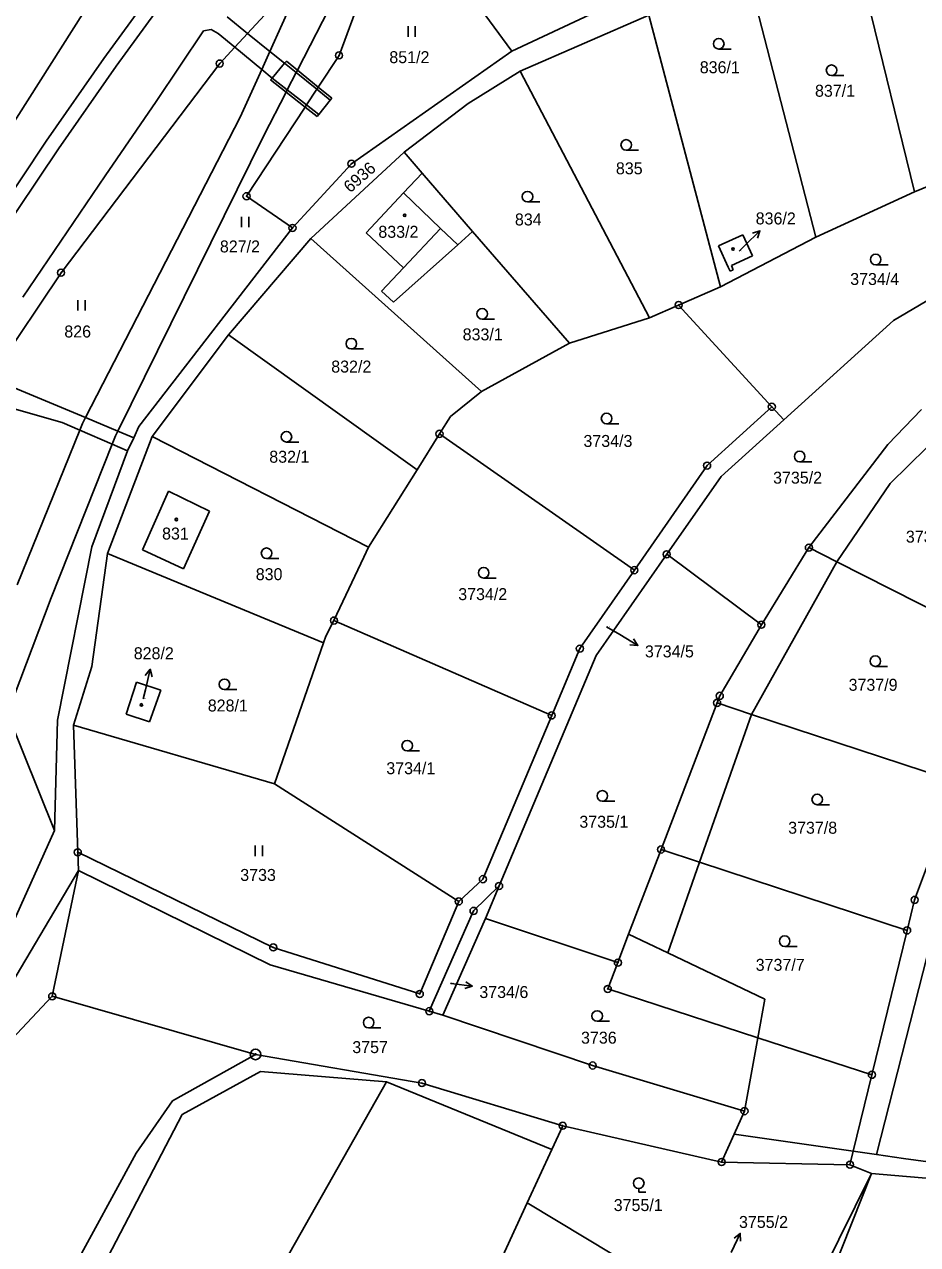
# Model space of a CAD drawing. Extents: x -593183 to -588034, y -1130415 to -1124994.
# Drawn here: x -592113.3 to -591986.4, y -1129180.7 to -1129007.5 of the extents above; entities that cross this region are included whole.
import ezdxf

# ---------------------------------------------------------------- set-up
doc = ezdxf.new("R2010")
doc.units = 0
for name, color, linetype in [('Vrstva 1', 7, 'Continuous'), ('Vrstva 16', 7, 'Continuous'), ('Vrstva 18', 7, 'Continuous'), ('Vrstva 19', 7, 'Continuous'), ('Vrstva 24', 7, 'Continuous'), ('Vrstva 25', 7, 'Continuous'), ('Vrstva 4', 7, 'Continuous')]:
    doc.layers.add(name, color=color, linetype=linetype)

msp = doc.modelspace()

# ---------------------------------------------------------------- linework, layer by layer
at = {"layer": 'Vrstva 1'}
for p, q in [((-592095.63, -1128991.25), (-592122.16, -1129033.04)), ((-592061.52, -1128993), (-592068.58, -1129011.91)), ((-592044.03, -1129011.3), (-592058.1, -1128992.14)), ((-592101.98, -1129012.35), (-592089.15, -1128994.78)), ((-592100.25, -1129013.46), (-592087.6, -1128996.06)), ((-591994.88, -1128998.43), (-591986.87, -1129031.29)), ((-592081.56, -1129008.78), (-592075.31, -1129002.03)), ((-592067.64, -1129000.62), (-592074.5, -1129014.01)), ((-592010.12, -1129001.94), (-592000.9, -1129037.72)), ((-592074.55, -1129002.77), (-592078.41, -1129011.34)), ((-592044.03, -1129011.3), (-592027.75, -1129003.63)), ((-592042.85, -1129014.16), (-592024.59, -1129006.21)), ((-592024.59, -1129006.21), (-592014.41, -1129044.75)), ((-592083.38, -1129010.75), (-592081.56, -1129008.78)), ((-592110.17, -1129024.09), (-592101.98, -1129012.35)), ((-592085.53, -1129013.07), (-592083.38, -1129010.75)), ((-592079.56, -1129013.91), (-592078.41, -1129011.34)), ((-592071.53, -1129016.4), (-592068.58, -1129011.91)), ((-592066.82, -1129027.29), (-592044.03, -1129011.3)), ((-592108.41, -1129025.19), (-592100.25, -1129013.46)), ((-592108.06, -1129042.75), (-592085.53, -1129013.07)), ((-592082.6, -1129020.67), (-592079.56, -1129013.91)), ((-592074.68, -1129014.35), (-592074.5, -1129014.01)), ((-592050.23, -1129018.75), (-592042.85, -1129014.16)), ((-592024.5, -1129049.14), (-592042.85, -1129014.16)), ((-592075.94, -1129016.81), (-592074.68, -1129014.35)), ((-592079.25, -1129023.26), (-592076.11, -1129017.13)), ((-592076.11, -1129017.13), (-592075.94, -1129016.81)), ((-592073.2, -1129018.94), (-592071.74, -1129016.71)), ((-592071.74, -1129016.71), (-592071.53, -1129016.4)), ((-592081.72, -1129031.9), (-592073.4, -1129019.25)), ((-592073.4, -1129019.25), (-592073.2, -1129018.94)), ((-592059.35, -1129025.66), (-592050.23, -1129018.75)), ((-592104.56, -1129063.33), (-592082.6, -1129020.67)), ((-591986.87, -1129031.29), (-591962.16, -1129021)), ((-592124.08, -1129044.93), (-592110.17, -1129024.09)), ((-592079.25, -1129023.26), (-592100, -1129065.24)), ((-592122.38, -1129045.9), (-592108.41, -1129025.19)), ((-592072.61, -1129037.9), (-592059.35, -1129025.66)), ((-592059.35, -1129025.66), (-592056.8, -1129028.61)), ((-592075.19, -1129036.4), (-592066.82, -1129027.29)), ((-592059.44, -1129031.43), (-592056.8, -1129028.61)), ((-592056.8, -1129028.61), (-592049.61, -1129036.91)), ((-592059.44, -1129031.43), (-592064.74, -1129037.09)), ((-592000.9, -1129037.72), (-591986.87, -1129031.29)), ((-592081.72, -1129031.9), (-592075.19, -1129036.4)), ((-591989.84, -1129049.54), (-591964.03, -1129034.3)), ((-592097.02, -1129064.6), (-592075.19, -1129036.4)), ((-592072.61, -1129037.9), (-592084.28, -1129051.58)), ((-592072.61, -1129037.9), (-592048.35, -1129059.62)), ((-592059.43, -1129042.06), (-592064.74, -1129037.09)), ((-592049.61, -1129036.91), (-592051.71, -1129038.78)), ((-592049.61, -1129036.91), (-592035.87, -1129052.78)), ((-592014.7, -1129038.95), (-592011.24, -1129037.37)), ((-592014.41, -1129044.75), (-592000.9, -1129037.72)), ((-592011.24, -1129037.37), (-592009.87, -1129040.37)), ((-592051.71, -1129038.78), (-592060.86, -1129046.95)), ((-592013.33, -1129041.95), (-592014.7, -1129038.95)), ((-592009.87, -1129040.37), (-592012.87, -1129041.75)), ((-592012.87, -1129041.75), (-592012.6, -1129042.34)), ((-592117.62, -1129057.03), (-592108.06, -1129042.75)), ((-592062.54, -1129045.38), (-592059.43, -1129042.06)), ((-592013.06, -1129042.55), (-592013.33, -1129041.95)), ((-592012.6, -1129042.34), (-592013.06, -1129042.55)), ((-592060.86, -1129046.95), (-592062.54, -1129045.38)), ((-592020.36, -1129047.34), (-592014.41, -1129044.75)), ((-592024.5, -1129049.14), (-592020.36, -1129047.34)), ((-592020.36, -1129047.34), (-592007.13, -1129061.79)), ((-592035.87, -1129052.78), (-592024.5, -1129049.14)), ((-592005.44, -1129063.63), (-591989.84, -1129049.54)), ((-592095.12, -1129066), (-592084.28, -1129051.58)), ((-592084.28, -1129051.58), (-592057.5, -1129070.72)), ((-592048.35, -1129059.62), (-592035.87, -1129052.78)), ((-592052.77, -1129063.17), (-592048.35, -1129059.62)), ((-592016.32, -1129070.14), (-592007.13, -1129061.79)), ((-592007.13, -1129061.79), (-592005.44, -1129063.63)), ((-591990.67, -1129067.13), (-591985.87, -1129062.19)), ((-592105.38, -1129065.12), (-592104.99, -1129064.16)), ((-592104.99, -1129064.16), (-592104.56, -1129063.33)), ((-592054.32, -1129065.63), (-592052.77, -1129063.17)), ((-592014.33, -1129071.66), (-592005.44, -1129063.63)), ((-592114.3, -1129087.06), (-592105.38, -1129065.12)), ((-592101.46, -1129082.61), (-592095.12, -1129066)), ((-592100.81, -1129067.11), (-592100.34, -1129065.92)), ((-592100, -1129065.24), (-592100.34, -1129065.92)), ((-592097.74, -1129066.19), (-592097.02, -1129064.6)), ((-592095.12, -1129066), (-592064.41, -1129081.73)), ((-592057.5, -1129070.72), (-592054.32, -1129065.63)), ((-592054.32, -1129065.63), (-592026.65, -1129084.98)), ((-592109.48, -1129088.92), (-592100.81, -1129067.11)), ((-592098.63, -1129068.06), (-592097.74, -1129066.19)), ((-592001.87, -1129081.78), (-591990.67, -1129067.13)), ((-592103.67, -1129081.65), (-592098.63, -1129068.06)), ((-592057.5, -1129070.72), (-592064.41, -1129081.73)), ((-592026.65, -1129084.98), (-592016.32, -1129070.14)), ((-592022.06, -1129082.73), (-592014.33, -1129071.66)), ((-592096.5, -1129082.09), (-592092.79, -1129073.78)), ((-592092.79, -1129073.78), (-592086.98, -1129076.61)), ((-592086.98, -1129076.61), (-592090.69, -1129084.78)), ((-592108.57, -1129106.26), (-592103.67, -1129081.65)), ((-592064.41, -1129081.73), (-592065.07, -1129083.14)), ((-592103.67, -1129098.65), (-592101.46, -1129082.61)), ((-592101.46, -1129082.61), (-592070.79, -1129095.3)), ((-592090.69, -1129084.78), (-592096.5, -1129082.09)), ((-592069.3, -1129092.13), (-592065.07, -1129083.14)), ((-592032.09, -1129097.08), (-592022.06, -1129082.73)), ((-592022.06, -1129082.73), (-592008.61, -1129092.72)), ((-592008.61, -1129092.72), (-592001.87, -1129081.78)), ((-592001.87, -1129081.78), (-591997.89, -1129083.8)), ((-592034.39, -1129096.11), (-592026.65, -1129084.98)), ((-591997.89, -1129083.8), (-591972.34, -1129096.74)), ((-592115.66, -1129105.33), (-592109.48, -1129088.92)), ((-592070.46, -1129094.36), (-592069.3, -1129092.13)), ((-592069.3, -1129092.13), (-592038.38, -1129105.6)), ((-592014.52, -1129102.82), (-592008.61, -1129092.72)), ((-592070.79, -1129095.3), (-592077.75, -1129115.29)), ((-592070.46, -1129094.36), (-592070.79, -1129095.3)), ((-592045.85, -1129129.81), (-592032.09, -1129097.08)), ((-592038.38, -1129105.6), (-592034.39, -1129096.11)), ((-592105.35, -1129103.97), (-592103.67, -1129098.65)), ((-592098.81, -1129105.4), (-592097.34, -1129100.88)), ((-592097.34, -1129100.88), (-592093.91, -1129101.99)), ((-592093.91, -1129101.99), (-592095.48, -1129106.49)), ((-592105.35, -1129103.97), (-592106.27, -1129106.98)), ((-592014.9, -1129103.82), (-592022.86, -1129124.63)), ((-592014.52, -1129102.82), (-592014.9, -1129103.82)), ((-592014.9, -1129103.82), (-592010.03, -1129105.49)), ((-592115.66, -1129105.33), (-592108.98, -1129121.92)), ((-592095.48, -1129106.49), (-592098.81, -1129105.4)), ((-592038.38, -1129105.6), (-592048.16, -1129128.84)), ((-592010.03, -1129105.49), (-591980.64, -1129115.09)), ((-592108.98, -1129121.92), (-592108.57, -1129106.26)), ((-592106.27, -1129106.98), (-592105.68, -1129125.02)), ((-592106.27, -1129106.98), (-592077.75, -1129115.29)), ((-592077.75, -1129115.29), (-592051.58, -1129132)), ((-591980.64, -1129115.09), (-591986.86, -1129131.78)), ((-592108.98, -1129121.92), (-592117.72, -1129141.31)), ((-592105.6, -1129127.62), (-592105.68, -1129125.02)), ((-592105.68, -1129125.02), (-592077.93, -1129138.52)), ((-592027.46, -1129136.67), (-592022.86, -1129124.63)), ((-592022.86, -1129124.63), (-592017.38, -1129126.43)), ((-592017.38, -1129126.43), (-591987.92, -1129136.12)), ((-592109.31, -1129145.46), (-592105.6, -1129127.62)), ((-592105.6, -1129127.62), (-592078.34, -1129140.99)), ((-592051.58, -1129132), (-592048.16, -1129128.84)), ((-592049.48, -1129133.34), (-592045.85, -1129129.81)), ((-592045.85, -1129129.81), (-592047.79, -1129134.42)), ((-591986.86, -1129131.78), (-591987.92, -1129136.12)), ((-592051.58, -1129132), (-592057.12, -1129145.14)), ((-592049.48, -1129133.34), (-592055.77, -1129147.58)), ((-592053.85, -1129148.14), (-592047.79, -1129134.42)), ((-592047.79, -1129134.42), (-592028.99, -1129140.69)), ((-592028.99, -1129140.69), (-592027.46, -1129136.67)), ((-591987.92, -1129136.12), (-591992.92, -1129156.61)), ((-592057.12, -1129145.14), (-592077.93, -1129138.52)), ((-592078.34, -1129140.99), (-592055.77, -1129147.58)), ((-592028.99, -1129140.69), (-592030.42, -1129144.42)), ((-592117.22, -1129153.83), (-592109.31, -1129145.46)), ((-592109.31, -1129145.46), (-592080.44, -1129153.72)), ((-592009.12, -1129151.34), (-592030.42, -1129144.42)), ((-592055.77, -1129147.58), (-592053.85, -1129148.14)), ((-592053.85, -1129148.14), (-592032.57, -1129155.29)), ((-591992.92, -1129156.61), (-592009.12, -1129151.34)), ((-592080.44, -1129153.72), (-592092.21, -1129160.3)), ((-592080.44, -1129153.72), (-592056.81, -1129157.78)), ((-592090.87, -1129162.25), (-592079.74, -1129156.12)), ((-592079.74, -1129156.12), (-592061.84, -1129157.63)), ((-592032.57, -1129155.29), (-592011.01, -1129161.77)), ((-592061.84, -1129157.63), (-592104.33, -1129232.5)), ((-592061.84, -1129157.63), (-592038.38, -1129167.21)), ((-592056.81, -1129157.78), (-592036.82, -1129163.84)), ((-591992.92, -1129156.61), (-591995.57, -1129167.46)), ((-592092.21, -1129160.3), (-592097.37, -1129167.74)), ((-592109.38, -1129197.76), (-592090.87, -1129162.25)), ((-592011.01, -1129161.77), (-592012.48, -1129165.04)), ((-592038.38, -1129167.21), (-592036.82, -1129163.84)), ((-592036.82, -1129163.84), (-592014.26, -1129168.99)), ((-592012.48, -1129165.04), (-592014.26, -1129168.99)), ((-592097.37, -1129167.74), (-592113.04, -1129196.42)), ((-592038.38, -1129167.21), (-592041.87, -1129174.78)), ((-591995.57, -1129167.46), (-591996.03, -1129169.37)), ((-592014.26, -1129168.99), (-591996.03, -1129169.37)), ((-591996.03, -1129169.37), (-591992.96, -1129170.62)), ((-592002.9, -1129190.64), (-591992.96, -1129170.62)), ((-591992.96, -1129170.62), (-592001.29, -1129191.44)), ((-591992.96, -1129170.62), (-591976.63, -1129172.04)), ((-592046.75, -1129185.36), (-592041.87, -1129174.78)), ((-592041.87, -1129174.78), (-592008.37, -1129194.92))]:
    msp.add_line(p, q, dxfattribs=at)
at = {"layer": 'Vrstva 16'}
for p, q in [((-592011.79, -1129039.7), (-592010.96, -1129038.89)), ((-592030.59, -1129093.02), (-592028.73, -1129094.13)), ((-592096.39, -1129103.25), (-592096.08, -1129101.97)), ((-592052.77, -1129143.61), (-592052.64, -1129143.63))]:
    msp.add_line(p, q, dxfattribs=at)
at = {"layer": 'Vrstva 24'}
for centre, radius in [((-592068.58, -1129011.91), 0.5), ((-592068.58, -1129011.91), 0.0327), ((-592085.53, -1129013.07), 0.5), ((-592085.53, -1129013.07), 0.0327), ((-592066.82, -1129027.29), 0.5), ((-592066.82, -1129027.29), 0.0327), ((-592081.72, -1129031.9), 0.5), ((-592081.72, -1129031.9), 0.0327), ((-592075.19, -1129036.4), 0.5), ((-592075.19, -1129036.4), 0.0327), ((-592108.06, -1129042.75), 0.5), ((-592108.06, -1129042.75), 0.0327), ((-592020.36, -1129047.34), 0.5), ((-592020.36, -1129047.34), 0.0327), ((-592007.13, -1129061.79), 0.5), ((-592007.13, -1129061.79), 0.0327), ((-592054.32, -1129065.63), 0.5), ((-592054.32, -1129065.63), 0.0327), ((-592016.32, -1129070.14), 0.5), ((-592016.32, -1129070.14), 0.0327), ((-592001.87, -1129081.78), 0.5), ((-592001.87, -1129081.78), 0.0327), ((-592022.06, -1129082.73), 0.5), ((-592022.06, -1129082.73), 0.0327), ((-592026.65, -1129084.98), 0.5), ((-592026.65, -1129084.98), 0.0327), ((-592069.3, -1129092.13), 0.5), ((-592069.3, -1129092.13), 0.0327), ((-592008.61, -1129092.72), 0.5), ((-592008.61, -1129092.72), 0.0327), ((-592034.39, -1129096.11), 0.5), ((-592034.39, -1129096.11), 0.0327), ((-592014.52, -1129102.82), 0.5), ((-592014.9, -1129103.82), 0.5), ((-592014.9, -1129103.82), 0.0327), ((-592014.52, -1129102.82), 0.0327), ((-592038.38, -1129105.6), 0.5), ((-592038.38, -1129105.6), 0.0327), ((-592105.68, -1129125.02), 0.5), ((-592105.68, -1129125.02), 0.0327), ((-592022.86, -1129124.63), 0.5), ((-592022.86, -1129124.63), 0.0327), ((-592048.16, -1129128.84), 0.5), ((-592048.16, -1129128.84), 0.0327), ((-592045.85, -1129129.81), 0.5), ((-592045.85, -1129129.81), 0.0327), ((-592051.58, -1129132), 0.5), ((-592051.58, -1129132), 0.0327), ((-591986.86, -1129131.78), 0.5), ((-591986.86, -1129131.78), 0.0327), ((-592049.48, -1129133.34), 0.5), ((-592049.48, -1129133.34), 0.0327), ((-591987.92, -1129136.12), 0.5), ((-591987.92, -1129136.12), 0.0327), ((-592077.93, -1129138.52), 0.5), ((-592077.93, -1129138.52), 0.0327), ((-592028.99, -1129140.69), 0.5), ((-592028.99, -1129140.69), 0.0327), ((-592030.42, -1129144.42), 0.5), ((-592109.31, -1129145.46), 0.5), ((-592109.31, -1129145.46), 0.0327), ((-592057.12, -1129145.14), 0.5), ((-592057.12, -1129145.14), 0.0327), ((-592030.42, -1129144.42), 0.0327), ((-592055.77, -1129147.58), 0.5), ((-592055.77, -1129147.58), 0.0327), ((-592080.44, -1129153.72), 0.75), ((-592080.44, -1129153.72), 0.0903), ((-592032.57, -1129155.29), 0.5), ((-592032.57, -1129155.29), 0.0327), ((-591992.92, -1129156.61), 0.5), ((-592056.81, -1129157.78), 0.5), ((-592056.81, -1129157.78), 0.0327), ((-591992.92, -1129156.61), 0.0327), ((-592011.01, -1129161.77), 0.5), ((-592011.01, -1129161.77), 0.0327), ((-592036.82, -1129163.84), 0.5), ((-592036.82, -1129163.84), 0.0327), ((-592014.26, -1129168.99), 0.5), ((-592014.26, -1129168.99), 0.0327), ((-591996.03, -1129169.37), 0.5), ((-591996.03, -1129169.37), 0.0327)]:
    msp.add_circle(centre, radius, dxfattribs=at)
at = {"layer": 'Vrstva 25'}
for p, q in [((-592058.78, -1129007.78), (-592058.78, -1129009.28)), ((-592057.76, -1129009.28), (-592057.76, -1129007.78)), ((-592012.92, -1129011.01), (-592014.67, -1129011.01)), ((-591996.9, -1129014.77), (-591998.65, -1129014.77)), ((-592026.05, -1129025.37), (-592027.8, -1129025.37)), ((-592040.07, -1129032.71), (-592041.82, -1129032.71)), ((-592082.43, -1129034.81), (-592082.43, -1129036.31)), ((-592081.41, -1129036.31), (-592081.41, -1129034.81)), ((-592010.96, -1129038.89), (-592008.81, -1129036.8)), ((-591990.63, -1129041.63), (-591992.38, -1129041.63)), ((-592105.66, -1129046.64), (-592105.66, -1129048.14)), ((-592104.64, -1129048.14), (-592104.64, -1129046.64)), ((-592046.51, -1129049.34), (-592048.26, -1129049.34)), ((-592065.09, -1129053.58), (-592066.84, -1129053.58)), ((-592028.84, -1129064.2), (-592030.59, -1129064.2)), ((-592074.3, -1129066.79), (-592076.05, -1129066.79)), ((-592001.43, -1129069.59), (-592003.18, -1129069.59)), ((-592077.12, -1129083.33), (-592078.87, -1129083.33)), ((-592046.29, -1129086.1), (-592048.04, -1129086.1)), ((-592028.73, -1129094.13), (-592026.15, -1129095.66)), ((-592096.08, -1129101.97), (-592095.38, -1129099.05)), ((-591990.69, -1129098.64), (-591992.44, -1129098.64)), ((-592083.11, -1129101.93), (-592084.86, -1129101.93)), ((-592057.15, -1129110.64), (-592058.9, -1129110.64)), ((-592029.44, -1129117.77), (-592031.19, -1129117.77)), ((-591998.93, -1129118.27), (-592000.68, -1129118.27)), ((-592080.49, -1129124.06), (-592080.49, -1129125.56)), ((-592079.47, -1129125.56), (-592079.47, -1129124.06)), ((-592003.55, -1129138.39), (-592005.3, -1129138.39)), ((-592052.64, -1129143.63), (-592049.66, -1129144.01)), ((-592030.18, -1129149.01), (-592031.93, -1129149.01)), ((-592062.63, -1129149.95), (-592064.38, -1129149.95)), ((-592026.03, -1129172.75), (-592026.03, -1129173.25)), ((-592026.03, -1129173.25), (-592025.01, -1129173.25)), ((-592012.9, -1129181.84), (-592011.62, -1129179.13))]:
    msp.add_line(p, q, dxfattribs=at)
for points in [[(-592009.88, -1129037.14), (-592008.81, -1129036.8), (-592009.18, -1129037.85)], [(-592026.76, -1129094.72), (-592026.15, -1129095.66), (-592027.27, -1129095.58)], [(-592096.1, -1129099.91), (-592095.38, -1129099.05), (-592095.13, -1129100.14)], [(-592050.59, -1129143.39), (-592049.66, -1129144.01), (-592050.72, -1129144.38)], [(-592012.5, -1129179.82), (-592011.62, -1129179.13), (-592011.6, -1129180.24)]]:
    msp.add_lwpolyline(points, dxfattribs=at)
for centre, radius in [((-592014.67, -1129010.26), 0.75), ((-591998.65, -1129014.02), 0.75), ((-592027.8, -1129024.62), 0.75), ((-592041.82, -1129031.96), 0.75), ((-592059.26, -1129034.6), 0.175), ((-592059.26, -1129034.6), 0.15), ((-592012.63, -1129039.4), 0.175), ((-592012.63, -1129039.4), 0.15), ((-591992.38, -1129040.88), 0.75), ((-592048.26, -1129048.59), 0.75), ((-592066.84, -1129052.83), 0.75), ((-592030.59, -1129063.45), 0.75), ((-592076.05, -1129066.04), 0.75), ((-592003.18, -1129068.84), 0.75), ((-592091.68, -1129077.79), 0.175), ((-592091.68, -1129077.79), 0.15), ((-592078.87, -1129082.58), 0.75), ((-592048.04, -1129085.35), 0.75), ((-591992.44, -1129097.89), 0.75), ((-592084.86, -1129101.18), 0.75), ((-592096.64, -1129104.1), 0.175), ((-592096.64, -1129104.1), 0.15), ((-592058.9, -1129109.89), 0.75), ((-592031.19, -1129117.02), 0.75), ((-592000.68, -1129117.52), 0.75), ((-592005.3, -1129137.64), 0.75), ((-592031.93, -1129148.26), 0.75), ((-592064.38, -1129149.2), 0.75), ((-592026.03, -1129172), 0.75)]:
    msp.add_circle(centre, radius, dxfattribs=at)
at = {"layer": 'Vrstva 4'}
for p, q in [((-592084.45, -1129006.44), (-592081.56, -1129008.78)), ((-592094.57, -1129018.44), (-592087.81, -1129008.44)), ((-592087.81, -1129008.44), (-592086.75, -1129008.25)), ((-592086.75, -1129008.25), (-592085.73, -1129008.81)), ((-592085.73, -1129008.81), (-592083.38, -1129010.75)), ((-592081.56, -1129008.78), (-592078.41, -1129011.34)), ((-592083.38, -1129010.75), (-592079.56, -1129013.91)), ((-592078.41, -1129011.34), (-592076.33, -1129013.02)), ((-592079.56, -1129013.91), (-592078.06, -1129015.15)), ((-592078.06, -1129015.15), (-592076.33, -1129013.02)), ((-592076.33, -1129013.02), (-592076.06, -1129012.75)), ((-592076.33, -1129013.02), (-592074.68, -1129014.35)), ((-592076.06, -1129012.75), (-592074.5, -1129014.01)), ((-592074.5, -1129014.01), (-592071.53, -1129016.4)), ((-592078.06, -1129015.15), (-592078.32, -1129015.4)), ((-592076.11, -1129017.13), (-592078.32, -1129015.4)), ((-592078.06, -1129015.15), (-592075.94, -1129016.81)), ((-592074.68, -1129014.35), (-592071.74, -1129016.71)), ((-592073.4, -1129019.25), (-592076.11, -1129017.13)), ((-592075.94, -1129016.81), (-592073.2, -1129018.94)), ((-592071.74, -1129016.71), (-592069.83, -1129018.25)), ((-592071.53, -1129016.4), (-592069.6, -1129017.96)), ((-592101.8, -1129029), (-592094.57, -1129018.44)), ((-592071.68, -1129020.6), (-592073.4, -1129019.25)), ((-592073.2, -1129018.94), (-592071.45, -1129020.31)), ((-592071.45, -1129020.31), (-592069.83, -1129018.25)), ((-592069.83, -1129018.25), (-592069.6, -1129017.96)), ((-592071.45, -1129020.31), (-592071.68, -1129020.6)), ((-592113.48, -1129046.22), (-592101.8, -1129029)), ((-592059.44, -1129031.43), (-592054.19, -1129036.46)), ((-592059.43, -1129042.06), (-592054.19, -1129036.46)), ((-592054.19, -1129036.46), (-592051.71, -1129038.78)), ((-592115.36, -1129058.8), (-592104.56, -1129063.33)), ((-592116.74, -1129061.49), (-592107.89, -1129064.03)), ((-592107.89, -1129064.03), (-592105.38, -1129065.12)), ((-592104.56, -1129063.33), (-592100, -1129065.24)), ((-592105.38, -1129065.12), (-592100.81, -1129067.11)), ((-592100, -1129065.24), (-592097.74, -1129066.19)), ((-591982.51, -1129065.01), (-591990.32, -1129072.67)), ((-592100.81, -1129067.11), (-592098.63, -1129068.06)), ((-591990.32, -1129072.67), (-591997.89, -1129083.8)), ((-591997.89, -1129083.8), (-592010.03, -1129105.49)), ((-592010.03, -1129105.49), (-592017.38, -1129126.43)), ((-592017.38, -1129126.43), (-592021.9, -1129139.32)), ((-592117.34, -1129147.43), (-592105.6, -1129127.62)), ((-591992.25, -1129167.94), (-591983.27, -1129132.66)), ((-592021.9, -1129139.32), (-592027.46, -1129136.67)), ((-592021.9, -1129139.32), (-592008.13, -1129145.88)), ((-592008.13, -1129145.88), (-592009.12, -1129151.34)), ((-592009.12, -1129151.34), (-592011.01, -1129161.77)), ((-592012.48, -1129165.04), (-591995.57, -1129167.46)), ((-591995.57, -1129167.46), (-591992.25, -1129167.94)), ((-591992.25, -1129167.94), (-591988.41, -1129168.49)), ((-591988.41, -1129168.49), (-591976.02, -1129170.14))]:
    msp.add_line(p, q, dxfattribs=at)

# ---------------------------------------------------------------- texts
at = {"layer": 'Vrstva 16'}
for s, p in [('836/2', (-592009.42, -1129035.9)), ('3734/5', (-592025.15, -1129097.36)), ('828/2', (-592097.73, -1129097.62)), ('3734/6', (-592048.66, -1129145.71)), ('3755/2', (-592011.79, -1129178.35))]:
    msp.add_text(s, height=1.7, dxfattribs=at).set_placement(p)
at = {"layer": 'Vrstva 18'}
for s, height, p in [('851/2', 1.7, (-592061.44, -1129013.01)), ('836/1', 1.7, (-592017.36, -1129014.44)), ('837/1', 1.7, (-592001, -1129017.78)), ('835', 1.7, (-592029.27, -1129028.79)), ('834', 1.7, (-592043.61, -1129036.05)), ('827/2', 1.7, (-592085.5, -1129039.88)), ('3734/4', 1.7, (-591996, -1129044.5)), ('826', 1.7, (-592107.59, -1129051.95)), ('833/1', 1.7, (-592051.03, -1129052.36)), ('832/2', 1.7, (-592069.69, -1129056.93)), ('3734/3', 1.7, (-592033.88, -1129067.49)), ('832/1', 1.7, (-592078.49, -1129069.73)), ('3735/2', 1.7, (-592006.95, -1129072.7)), ('3737/10', 1.7, (-591988.1, -1129081.07)), ('830', 1.7, (-592080.41, -1129086.4)), ('3734/2', 1.7, (-592051.66, -1129089.23)), ('3734/5', 0.1, (-592030.59, -1129093.02)), ('3737/9', 1.7, (-591996.23, -1129102.1)), ('828/1', 1.7, (-592087.22, -1129105.04)), ('3734/1', 1.7, (-592061.87, -1129113.94)), ('3735/1', 1.7, (-592034.46, -1129121.54)), ('3737/8', 1.7, (-592004.81, -1129122.39)), ('3733', 1.7, (-592082.61, -1129129.09)), ('3737/7', 1.7, (-592009.42, -1129141.85)), ('3734/6', 0.1, (-592052.77, -1129143.61)), ('3736', 1.7, (-592034.22, -1129152.19)), ('3757', 1.7, (-592066.7, -1129153.53)), ('3755/1', 1.7, (-592029.58, -1129175.95))]:
    msp.add_text(s, height=height, dxfattribs=at).set_placement(p)
msp.add_text('6936', height=1.7, rotation=41.3628, dxfattribs=at).set_placement((-592067.01, -1129031.5))
at = {"layer": 'Vrstva 19'}
for s, height, p in [('833/2', 1.7, (-592063, -1129037.8)), ('836/2', 0.1, (-592011.79, -1129039.7)), ('831', 1.7, (-592093.71, -1129080.63)), ('828/2', 0.1, (-592096.39, -1129103.25))]:
    msp.add_text(s, height=height, dxfattribs=at).set_placement(p)

doc.saveas('drawing.dxf')
